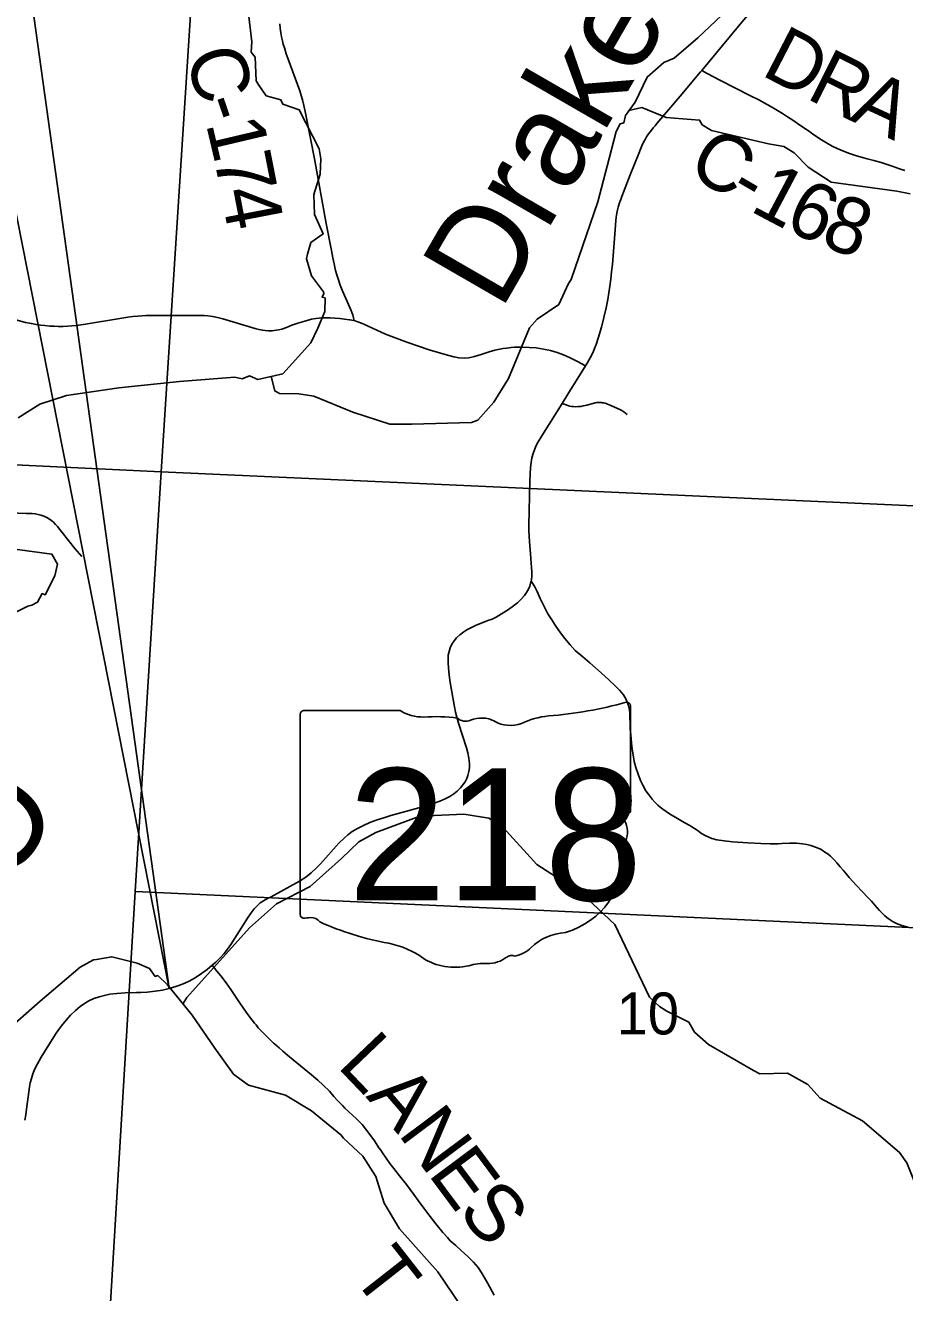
# Model space of a CAD drawing. Extents: x 0 to 34, y 0 to 22.
# Drawn here: x 27.118 to 27.996, y 17.66 to 18.925 of the extents above; entities that cross this region are included whole.
import ezdxf

# ---------------------------------------------------------------- set-up
doc = ezdxf.new("R2010")
doc.units = 0
for name, color, linetype in [('GM_X_County_Road', 7, 'Continuous'), ('GM_X_County_Road_Text', 7, 'Continuous'), ('GM_X_Minor_River', 7, 'Continuous'), ('GM_X_Minor_River_Text', 7, 'Continuous'), ('GM_X_Section', 7, 'Continuous'), ('GM_X_Section_Text', 7, 'Continuous'), ('GM_X_State_Location', 7, 'Continuous'), ('GM_X_State_Route', 7, 'Continuous'), ('GM_X_State_Shield', 7, 'Continuous'), ('GM_X_Township_Road', 7, 'Continuous'), ('GM_X_Township_Road_Text', 7, 'Continuous'), ('SH_Text', 7, 'Continuous')]:
    doc.layers.add(name, color=color, linetype=linetype)

msp = doc.modelspace()

# ---------------------------------------------------------------- linework, layer by layer
at = {"layer": 'GM_X_County_Road'}
for points in [[(27.4468, 18.6301), (27.4461, 18.633), (27.4453, 18.6359), (27.4445, 18.6381), (27.4433, 18.6409), (27.4348, 18.6604), (27.4327, 18.6656), (27.4306, 18.6719), (27.4294, 18.6758), (27.4281, 18.6802), (27.4266, 18.6868), (27.4255, 18.6929), (27.4242, 18.7002), (27.4189, 18.7271), (27.4072, 18.7917), (27.4032, 18.8118), (27.3977, 18.8389), (27.3965, 18.8449), (27.3951, 18.8506), (27.3939, 18.8548), (27.3924, 18.8596), (27.3807, 18.8911), (27.3788, 18.8965), (27.377, 18.9022), (27.3759, 18.906), (27.3751, 18.9094), (27.3743, 18.9134), (27.3736, 18.9174), (27.3729, 18.922), (27.3724, 18.9264)], [(27.7937, 18.8799), (27.7993, 18.8769), (27.8125, 18.8697), (27.8274, 18.862), (27.8425, 18.8546), (27.8508, 18.8504), (27.8561, 18.8475), (27.862, 18.8441), (27.8677, 18.8407), (27.8743, 18.8367), (27.8792, 18.8336), (27.8846, 18.8301), (27.8937, 18.824), (27.9014, 18.8187), (27.9048, 18.8163), (27.9132, 18.8105), (27.9183, 18.8074), (27.9241, 18.8043), (27.929, 18.8019), (27.937, 18.7985), (27.9411, 18.797), (27.9482, 18.7947), (27.9541, 18.793), (27.9589, 18.7917), (27.9654, 18.79), (27.973, 18.7879), (27.9839, 18.7842), (27.9913, 18.7817), (27.9964, 18.7799)], [(27.1089, 18.6307), (27.1187, 18.6283), (27.1245, 18.6271), (27.1291, 18.6263), (27.1336, 18.6256), (27.138, 18.6251), (27.1429, 18.6247), (27.1471, 18.6245), (27.1513, 18.6243), (27.156, 18.6243), (27.1607, 18.6245), (27.1647, 18.6249), (27.169, 18.6253), (27.1737, 18.6259), (27.1783, 18.6266), (27.2148, 18.6325), (27.2206, 18.6334), (27.2258, 18.6341), (27.2306, 18.6346), (27.2347, 18.6349), (27.2387, 18.6351), (27.2881, 18.6353), (27.2929, 18.6352), (27.2969, 18.6351), (27.3005, 18.6348), (27.3056, 18.6341), (27.3104, 18.6331), (27.3157, 18.6318), (27.3488, 18.6219), (27.3518, 18.6211), (27.3551, 18.6205), (27.358, 18.6201), (27.3613, 18.6199), (27.3647, 18.62), (27.3688, 18.6204), (27.3716, 18.6209), (27.3744, 18.6216), (27.3792, 18.6232), (27.3846, 18.6254), (27.3906, 18.6277), (27.3973, 18.6297), (27.4041, 18.6315), (27.4084, 18.6322), (27.4117, 18.6326), (27.415, 18.6328), (27.4182, 18.6328), (27.4227, 18.6327), (27.4275, 18.6325), (27.4324, 18.6321), (27.4371, 18.6316), (27.4422, 18.631), (27.4468, 18.6301), (27.4505, 18.6289), (27.4539, 18.6277), (27.4569, 18.6263), (27.4608, 18.6246), (27.4781, 18.6166), (27.4993, 18.6086), (27.5217, 18.601), (27.5399, 18.5956), (27.5461, 18.594), (27.5512, 18.5931), (27.5564, 18.5927), (27.5613, 18.593), (27.5669, 18.5942), (27.5735, 18.5962), (27.5816, 18.5989), (27.587, 18.6005), (27.5923, 18.6017), (27.5956, 18.6022), (27.5988, 18.6027), (27.6033, 18.6032), (27.6069, 18.6035), (27.6108, 18.6037), (27.6148, 18.6036), (27.6215, 18.6034), (27.6283, 18.6029), (27.6356, 18.6017), (27.6428, 18.6001), (27.6493, 18.5983), (27.6557, 18.596), (27.6625, 18.593), (27.6696, 18.5893), (27.6778, 18.5851)], [(27.9996, 18.0245), (27.9936, 18.0263), (27.9883, 18.0283), (27.985, 18.03), (27.9807, 18.0327), (27.9784, 18.0343), (27.9763, 18.0363), (27.9742, 18.0382), (27.9713, 18.0412), (27.9666, 18.0466), (27.9632, 18.0505), (27.9593, 18.0547), (27.9545, 18.0597), (27.9475, 18.067), (27.9449, 18.07), (27.9409, 18.0744), (27.9383, 18.0774), (27.9349, 18.0814), (27.9319, 18.085), (27.9286, 18.089), (27.9261, 18.0918), (27.9222, 18.0955), (27.9195, 18.0977), (27.9176, 18.099), (27.9139, 18.1015), (27.9123, 18.1024), (27.91, 18.1034), (27.9073, 18.1045), (27.9027, 18.1062), (27.8985, 18.1072), (27.8943, 18.108), (27.8883, 18.1085), (27.8815, 18.1084), (27.8736, 18.1081), (27.87, 18.1079), (27.8662, 18.108), (27.8619, 18.1079), (27.8528, 18.1082), (27.8399, 18.1088), (27.8246, 18.1098), (27.816, 18.1108), (27.8087, 18.112), (27.8038, 18.1133), (27.8008, 18.1144), (27.7973, 18.116), (27.7936, 18.1182), (27.789, 18.1214), (27.7838, 18.1248), (27.7817, 18.126), (27.7763, 18.129), (27.7678, 18.134), (27.7625, 18.1372), (27.7582, 18.1402), (27.7548, 18.1425), (27.7522, 18.1445), (27.7499, 18.1465), (27.7472, 18.149), (27.7442, 18.1523), (27.7411, 18.1563), (27.7379, 18.1609), (27.7348, 18.1664), (27.7327, 18.1709), (27.7301, 18.1773), (27.7279, 18.1839), (27.7264, 18.1899), (27.7251, 18.1967), (27.7242, 18.2022), (27.7235, 18.2084), (27.7228, 18.2165), (27.7224, 18.2227), (27.7222, 18.229), (27.722, 18.2333), (27.7218, 18.2388), (27.7213, 18.2428), (27.7206, 18.246), (27.7194, 18.2494), (27.7184, 18.2519), (27.717, 18.2544), (27.7156, 18.2566), (27.714, 18.2587), (27.7117, 18.2612), (27.7079, 18.265), (27.701, 18.2715), (27.6933, 18.2784), (27.682, 18.2884), (27.675, 18.2944), (27.6675, 18.3009), (27.6624, 18.3064), (27.657, 18.3127), (27.6518, 18.3199), (27.6473, 18.3261), (27.6439, 18.3313), (27.6402, 18.3375), (27.6364, 18.3446), (27.6325, 18.3526), (27.6293, 18.3598), (27.6274, 18.3637), (27.6255, 18.3669), (27.6233, 18.3701)]]:
    msp.add_lwpolyline(points, dxfattribs=at)
at = {"layer": 'GM_X_Minor_River'}
for points in [[(27.1112, 18.5331), (27.1327, 18.5468), (27.1595, 18.5553), (27.2117, 18.563), (27.2722, 18.5692), (27.3277, 18.5735), (27.3349, 18.572), (27.3421, 18.5751), (27.3504, 18.5713), (27.3754, 18.5771), (27.4033, 18.6079), (27.4105, 18.6224), (27.4173, 18.6391), (27.4176, 18.6528), (27.4146, 18.6535), (27.4165, 18.657), (27.4161, 18.6589), (27.404, 18.6748), (27.3991, 18.6919), (27.4002, 18.6964), (27.4036, 18.7079), (27.4157, 18.7166), (27.407, 18.736), (27.4066, 18.7561), (27.4126, 18.7763), (27.4134, 18.7915), (27.4118, 18.8014), (27.3918, 18.8405), (27.3755, 18.8461), (27.3736, 18.8503), (27.3589, 18.8545), (27.3509, 18.8662), (27.349, 18.8693), (27.3479, 18.8932), (27.3437, 18.8981), (27.3444, 18.9084), (27.3414, 18.9338)], [(27.3638, 18.5744), (27.3674, 18.5599), (27.372, 18.5573), (27.3916, 18.557), (27.4064, 18.5547), (27.4453, 18.5388), (27.4824, 18.5268), (27.5043, 18.5268), (27.5637, 18.5285), (27.5701, 18.5308), (27.586, 18.5487), (27.6007, 18.5723), (27.6218, 18.6229), (27.6294, 18.6316), (27.6509, 18.6461), (27.6607, 18.667), (27.6633, 18.6712), (27.6901, 18.7488), (27.7014, 18.7918), (27.7082, 18.8188), (27.7123, 18.8264), (27.7161, 18.8275), (27.7176, 18.8348), (27.7274, 18.8481), (27.7391, 18.8732), (27.7558, 18.8877), (27.7663, 18.8919), (27.7898, 18.9125), (27.8139, 18.9349)], [(27.7209, 18.8399), (27.734, 18.8427), (27.7583, 18.8329), (27.7915, 18.8303), (27.794, 18.8256), (27.8036, 18.82), (27.8605, 18.8064)], [(27.8605, 18.8064), (27.8757, 18.804), (27.8861, 18.7976), (27.9, 18.7831), (27.923, 18.7684), (27.9885, 18.7594), (28.0017, 18.7567)], [(27.0902, 18.3297), (27.1208, 18.345), (27.1249, 18.3462), (27.1306, 18.3492), (27.1351, 18.3576), (27.1382, 18.3565), (27.148, 18.3755), (27.1506, 18.3869), (27.1449, 18.3971), (27.1079, 18.402)], [(27.2759, 17.9485), (27.2795, 17.9544), (27.3421, 18.0241), (27.3693, 18.0479), (27.4027, 18.0651), (27.4342, 18.0933), (27.4513, 18.1099), (27.4683, 18.1192), (27.5122, 18.1356), (27.5561, 18.1373), (27.581, 18.1334), (27.5954, 18.1242), (27.6291, 18.0871), (27.6739, 18.0583), (27.707, 18.0273), (27.7415, 17.9548), (27.7514, 17.9454), (27.7588, 17.9409), (27.7808, 17.93), (27.7865, 17.9199), (27.8005, 17.9077), (27.8455, 17.8815)], [(27.1053, 17.9262), (27.1332, 17.9509), (27.1733, 17.9849), (27.1865, 17.9921), (27.1895, 17.9925), (27.2047, 17.9952), (27.23, 17.9888), (27.2425, 17.9835), (27.2481, 17.9755), (27.2508, 17.9763), (27.2602, 17.9672), (27.2848, 17.9368), (27.3076, 17.9038), (27.3261, 17.878), (27.3352, 17.8712), (27.3412, 17.867), (27.3783, 17.8569), (27.404, 17.8413), (27.4335, 17.8175), (27.4362, 17.8141), (27.4555, 17.7962), (27.4683, 17.7758), (27.4767, 17.7492), (27.4918, 17.7237), (27.5304, 17.6805), (27.5698, 17.6221)], [(27.8455, 17.8815), (27.8518, 17.8784), (27.8794, 17.879), (27.8995, 17.8677), (27.9119, 17.854), (27.9543, 17.8314), (27.9912, 17.7999), (27.9984, 17.7894), (28.0128, 17.754), (28.0157, 17.7478), (28.0648, 17.722), (28.1145, 17.7181), (28.1413, 17.7142), (28.2012, 17.6975), (28.2224, 17.6964), (28.2435, 17.6938), (28.3072, 17.6656), (28.3329, 17.6633), (28.3692, 17.6762), (28.4131, 17.6801), (28.4343, 17.6938), (28.4405, 17.6978), (28.4784, 17.7251)]]:
    msp.add_lwpolyline(points, dxfattribs=at)
at = {"layer": 'GM_X_Section'}
for points in [[(26.2655, 19.5533), (27.3196, 19.501), (27.254, 18.479), (26.2062, 18.5294)], [(27.3196, 19.501), (28.356, 19.4486), (28.293, 18.4323), (27.254, 18.479)], [(26.2062, 18.5294), (27.254, 18.479), (27.228, 18.0601), (27.2029, 17.6387), (27.1952, 17.4804), (26.5953, 17.5088), (26.1481, 17.5351), (26.1482, 17.5386), (26.1578, 17.7173), (26.1806, 18.1307)], [(27.254, 18.479), (28.293, 18.4323), (28.2659, 18.0119), (27.228, 18.0601)], [(28.2659, 18.0119), (28.2386, 17.5871), (27.2029, 17.6387), (27.228, 18.0601)]]:
    msp.add_lwpolyline(points, close=True, dxfattribs=at)
at = {"layer": 'GM_X_State_Route'}
msp.add_lwpolyline([(27.1178, 17.8319), (27.1188, 17.8373), (27.1197, 17.8429), (27.1218, 17.8604), (27.1225, 17.8654), (27.1232, 17.8694), (27.1244, 17.8737), (27.126, 17.8783), (27.128, 17.8831), (27.1306, 17.8882), (27.1342, 17.8949), (27.1486, 17.9179), (27.1516, 17.9222), (27.1544, 17.9261), (27.159, 17.9319), (27.1635, 17.9369), (27.1684, 17.9416), (27.1731, 17.9455), (27.1776, 17.9486), (27.1819, 17.951), (27.1869, 17.9533), (27.1921, 17.9551), (27.1974, 17.9566), (27.2029, 17.9577), (27.2096, 17.9585), (27.2182, 17.9591), (27.2293, 17.9593), (27.2337, 17.9594), (27.2399, 17.9598), (27.248, 17.9607), (27.2554, 17.9619), (27.2621, 17.9634), (27.2687, 17.9654), (27.2752, 17.9679), (27.282, 17.9709), (27.2881, 17.9742), (27.2944, 17.9783), (27.2999, 17.9825), (27.305, 17.9866), (27.3085, 17.9898), (27.3126, 17.9937), (27.3168, 17.9983), (27.3204, 18.0026), (27.3237, 18.0072), (27.3402, 18.0335), (27.344, 18.0391), (27.347, 18.043), (27.3497, 18.046), (27.3513, 18.0474), (27.353, 18.0488), (27.3563, 18.051), (27.3601, 18.0532), (27.3637, 18.0551), (27.3921, 18.0705), (27.3984, 18.0746), (27.4038, 18.0788), (27.4089, 18.0835), (27.4132, 18.088), (27.4314, 18.1084), (27.4367, 18.1136), (27.4404, 18.1168), (27.4448, 18.12), (27.45, 18.1233), (27.4561, 18.1263), (27.4623, 18.129), (27.4698, 18.1318), (27.4764, 18.1339), (27.4834, 18.136), (27.5187, 18.1458), (27.5266, 18.1483), (27.5322, 18.1504), (27.5375, 18.1527), (27.5421, 18.155), (27.5463, 18.1577), (27.5497, 18.1605), (27.5529, 18.1636), (27.5553, 18.1666), (27.5574, 18.1698), (27.5592, 18.1732), (27.5603, 18.1762), (27.5612, 18.1799), (27.5617, 18.1837), (27.5617, 18.1881), (27.5613, 18.1932), (27.5603, 18.1987), (27.559, 18.2036), (27.551, 18.2284), (27.5492, 18.2342), (27.548, 18.2391), (27.5468, 18.2445), (27.5425, 18.2688), (27.5416, 18.2763), (27.5408, 18.2835), (27.5405, 18.2884), (27.5404, 18.2926), (27.5406, 18.296), (27.5414, 18.2998), (27.5424, 18.3034), (27.5441, 18.307), (27.5464, 18.3104), (27.5489, 18.3133), (27.5522, 18.3166), (27.5561, 18.3195), (27.5593, 18.3216), (27.5637, 18.3239), (27.5677, 18.3257), (27.5803, 18.3306), (27.5844, 18.3322), (27.5884, 18.3342), (27.6007, 18.3416), (27.6058, 18.3453), (27.6097, 18.3484), (27.6136, 18.352), (27.6168, 18.3556), (27.6189, 18.3587), (27.6209, 18.3622), (27.622, 18.365), (27.6229, 18.3679), (27.6233, 18.3701), (27.6236, 18.3713), (27.624, 18.3754), (27.6241, 18.3797), (27.6239, 18.3834), (27.6227, 18.3974), (27.6216, 18.4095), (27.6213, 18.4153), (27.6212, 18.4204), (27.6212, 18.4258), (27.6221, 18.4692), (27.6224, 18.4773), (27.6228, 18.4836), (27.6233, 18.4884), (27.6242, 18.4932), (27.6254, 18.4974), (27.6268, 18.5012), (27.6282, 18.5047), (27.6304, 18.509), (27.634, 18.515), (27.6543, 18.5474), (27.6601, 18.5567), (27.6778, 18.5851), (27.6795, 18.5877), (27.6823, 18.5928), (27.6849, 18.598), (27.6867, 18.6022), (27.6883, 18.6063), (27.6903, 18.6125), (27.6936, 18.6237), (27.6983, 18.643), (27.6999, 18.651), (27.702, 18.6646), (27.7029, 18.6713), (27.7038, 18.6787), (27.7046, 18.6862), (27.7072, 18.7207), (27.7075, 18.7256), (27.7079, 18.7298), (27.7083, 18.7333), (27.7089, 18.7372), (27.7096, 18.7405), (27.7103, 18.7433), (27.711, 18.7458), (27.7119, 18.7485), (27.7128, 18.7509), (27.714, 18.7541), (27.7224, 18.7757), (27.7308, 18.7969), (27.7325, 18.8011), (27.734, 18.8045), (27.7354, 18.8075), (27.7371, 18.8107), (27.7387, 18.8136), (27.7405, 18.8165), (27.7425, 18.819), (27.7452, 18.8224), (27.7471, 18.8246), (27.749, 18.8269), (27.7721, 18.8541), (27.7925, 18.8785), (27.7937, 18.8799), (27.8289, 18.922), (27.8515, 18.949)], dxfattribs=at)
at = {"layer": 'GM_X_State_Shield'}
for p, q in [((27.4927, 18.2408), (27.3961, 18.2408)), ((27.7225, 18.1411), (27.7225, 18.2457)), ((27.3929, 18.2373), (27.3929, 18.0372)), ((27.7224, 18.1411), (27.7225, 18.1411))]:
    msp.add_line(p, q, dxfattribs=at)
for centre, major_axis, start_param, end_param in [((27.3967, 18.2378), (0.00382, 0), 1.712693, 3.28349), ((27.5156, 18.264), (0.037, 0), 4.042523, 4.731795), ((27.6051, 18.5136), (0.3495, 0), 4.814394, 5.042369), ((27.7188, 18.2462), (0.00367, 0), 6.141152, 7.989035), ((27.5279, 18.1284), (0.133, 0), 1.404758, 1.657858), ((27.5581, 18.2388), (0.0107, 0), 3.836095, 5.185415), ((27.5738, 18.2157), (0.0222, 0), 0.950623, 2.079405), ((27.6025, 18.2474), (0.0267, 0), 4.081561, 5.145723), ((27.6497, 18.1797), (0.0703, 0), 1.699011, 2.107814), ((27.7186, 18.1407), (0.00393, 0), 5.05454, 6.418171), ((27.7216, 18.1334), (0.00568, 0), 1.883978, 3.671073), ((27.6855, 18.1201), (0.0341, 0), 5.934695, 6.695948), ((27.7356, 18.0972), (0.0248, 0), 2.387724, 3.262537), ((27.6246, 18.0839), (0.0874, 0), 5.101752, 6.440018), ((27.3967, 18.0368), (0.00385, 0), 3.00124, 4.508301), ((27.3973, 18.0573), (0.0294, 0), 4.665946, 4.897461), ((27.4033, 18.0257), (0.0106, 0), 0.519207, 1.627899), ((27.5371, 18.2055), (0.2524, 0), 4.195997, 4.488961), ((27.6615, 17.981), (0.0479, 0), 1.647645, 2.488434), ((27.4619, 17.9473), (0.079, 0), 0.823519, 1.323587), ((27.6008, 18.0178), (0.0282, 0), 4.937069, 5.64225), ((27.5473, 18.0247), (0.0501, 0), 4.026481, 4.996735), ((27.5762, 17.9555), (0.0412, 0), 1.495662, 1.94098), ((27.5799, 18.0097), (0.0267, 0), 4.691044, 5.507374), ((27.6041, 17.9903), (0.00752, 0), 1.147584, 2.315152)]:
    msp.add_ellipse(centre, major_axis=major_axis, ratio=0.8, start_param=start_param, end_param=end_param, dxfattribs=at)
at = {"layer": 'GM_X_Township_Road'}
for points in [[(27.6543, 18.5474), (27.6573, 18.5463), (27.66, 18.5453), (27.6617, 18.5448), (27.6636, 18.5444), (27.6658, 18.5442), (27.668, 18.5441), (27.6704, 18.5442), (27.673, 18.5445), (27.6752, 18.5449), (27.6772, 18.5453), (27.6789, 18.5458), (27.6862, 18.5477), (27.6873, 18.548), (27.6885, 18.5482), (27.6898, 18.5483), (27.691, 18.5484), (27.6923, 18.5483), (27.6936, 18.5483), (27.6948, 18.5481), (27.696, 18.5479), (27.6973, 18.5476), (27.6984, 18.5473), (27.6995, 18.5468), (27.7008, 18.5463), (27.7118, 18.5415), (27.714, 18.5404), (27.7158, 18.5392), (27.7176, 18.5378), (27.7193, 18.5363)], [(27.095, 18.4384), (27.1193, 18.4377), (27.1252, 18.4376), (27.1283, 18.4373), (27.1311, 18.4367), (27.134, 18.4359), (27.1369, 18.4348), (27.1398, 18.4335), (27.1425, 18.4319), (27.1447, 18.4304), (27.1466, 18.4288), (27.1486, 18.4266), (27.1504, 18.4245), (27.1553, 18.4185), (27.1678, 18.4026), (27.1748, 18.3947)], [(27.305, 17.9866), (27.3097, 17.9809), (27.3137, 17.976), (27.3189, 17.969), (27.3235, 17.9623), (27.3328, 17.9484), (27.3389, 17.9399), (27.3426, 17.9349), (27.3471, 17.929), (27.3487, 17.9271), (27.351, 17.9243), (27.3557, 17.9193), (27.3635, 17.9115), (27.3662, 17.909), (27.3671, 17.9082), (27.3694, 17.9061), (27.3717, 17.9041), (27.3754, 17.9009), (27.3778, 17.8989), (27.3802, 17.8969), (27.3859, 17.8922), (27.393, 17.8863), (27.4041, 17.8774), (27.4103, 17.8721), (27.4158, 17.8671), (27.422, 17.8609), (27.4265, 17.8558), (27.4298, 17.8521), (27.4327, 17.8489), (27.435, 17.8467), (27.4375, 17.8441), (27.4489, 17.8335), (27.4546, 17.8277), (27.4591, 17.8222), (27.4652, 17.8138), (27.4669, 17.8113), (27.4703, 17.806), (27.4714, 17.8045), (27.4732, 17.8021), (27.4749, 17.7995), (27.4824, 17.7888), (27.4863, 17.7839), (27.4919, 17.7765), (27.4988, 17.7678), (27.5063, 17.7579), (27.5106, 17.7518), (27.5162, 17.7443), (27.5202, 17.7388), (27.5281, 17.7285), (27.5351, 17.7199), (27.5398, 17.7149), (27.5427, 17.7117), (27.5482, 17.7068), (27.5537, 17.7018), (27.5602, 17.6959), (27.566, 17.6902), (27.5704, 17.6849), (27.5743, 17.6792), (27.5802, 17.6689), (27.5864, 17.6575)]]:
    msp.add_lwpolyline(points, dxfattribs=at)
at = {"layer": 'SH_Text'}
msp.add_lwpolyline([(27.0492, 19.0391), (27.2621, 17.9634), (27.0492, 19.4888)], close=True, dxfattribs=at)

# ---------------------------------------------------------------- texts
at = {"layer": 'GM_X_County_Road_Text'}
for s, rotation, p in [('D', 332.6448, (27.8517, 18.8758)), ('C', 285.9744, (27.2778, 18.8954)), ('R', 333.3021, (27.8967, 18.8525)), ('A', 335.2103, (27.9403, 18.8306)), ('-', 288.6765, (27.2915, 18.8477)), ('1', 283.2417, (27.2985, 18.827)), ('C', 328.6259, (27.7772, 18.7782)), ('7', 281.139, (27.3064, 18.7935)), ('-', 329.6337, (27.818, 18.7534)), ('1', 332.1583, (27.8405, 18.7402)), ('4', 280.916, (27.3132, 18.7592)), ('6', 335.1745, (27.8744, 18.7224)), ('8', 339.4981, (27.9105, 18.7059))]:
    msp.add_text(s, height=0.0568, rotation=rotation, dxfattribs=at).set_placement(p)
at = {"layer": 'GM_X_Minor_River_Text'}
for s, rotation, p in [('Drakes', 59.9948, (27.5929, 18.6388)), ('Creek', 236.1304, (27.0759, 18.1964))]:
    msp.add_text(s, height=0.09469, rotation=rotation, dxfattribs=at).set_placement(p)
at = {"layer": 'GM_X_Section_Text'}
msp.add_text('10', height=0.04186, rotation=0, dxfattribs=at).set_placement((27.7088, 17.9176))
at = {"layer": 'GM_X_State_Location'}
for s in ['s', 'r']:
    msp.add_text(s, height=0.000189, dxfattribs=at).set_placement((27.554, 18.124))
msp.add_text('218', height=0.000189, rotation=0, dxfattribs=at).set_placement((27.4871, 18.1102))
at = {"layer": 'GM_X_State_Shield'}
msp.add_text('218', height=0.13184, dxfattribs=at).set_placement((27.4405, 18.0513))
at = {"layer": 'GM_X_Township_Road_Text'}
for s, rotation, p in [('L', 313.7196, (27.4288, 17.8857)), ('A', 310.7937, (27.4577, 17.8555)), ('N', 306.8054, (27.4897, 17.8185)), ('E', 306.7165, (27.5196, 17.7785)), ('S', 312.0447, (27.5487, 17.7399)), ('T', 308.0554, (27.4429, 17.6773))]:
    msp.add_text(s, height=0.0568, rotation=rotation, dxfattribs=at).set_placement(p)

doc.saveas('drawing.dxf')
